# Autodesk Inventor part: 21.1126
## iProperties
Created: 2006-02
Part Number: 21.1126
Material: Steel, Mild
Description: M6 ROUND WASHER DIN 125-1A
Document SubType Name: Modeling
Standard: DIN 125
Designer: Andy Moles
Standards Organization: DIN
Language: en-US
Size Designation: A 6.4
Categories: <MemberInstance><Categories><Category DisplayName="Fasteners" InternalName="e4da775c-781d-43d5-af7c-5136215cf5a6" Mnemonic="FSTN"><Category DisplayName="Washers
Density: 1 g/cm^3
Author: Andy Moles
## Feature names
1. Body [Extrusion]
